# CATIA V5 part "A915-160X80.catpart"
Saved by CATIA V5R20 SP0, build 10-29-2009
Part number: A915-160X80
Source: Unknown
Property "A": "110.000"
Property "ARTICLENO": "A915-160X80"
Property "BOMINFO": "A915-160X80"
Property "CODE": "A915-160X80"
Property "CREATOR": "CADENAS GmbH"
Property "D": "13.500"
Property "D1": "20.000"
Property "FORM": "A"
Property "L": "80.000"
Property "L1": "40.000"
Property "L2": "0.000"
Property "LINA": "A915-160X80"
Property "NB": "A915-160X80"
Property "NBSYN": "$CODE."
Property "NN": "A915"
Property "NT": "VDI 3357 Wear Plates, steel"
Property "SCREW": "M12x25"
Property "SUPPLIER": "CF"
Property "T": "13.000"
Property "W": "160.000"
Bounding box of the stored display mesh (mm): x 0 to 20, y 0 to 80, z -80 to 80
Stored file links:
  C:\Users\borellobunino\Desktop\3D X SITO CF\A915\GSB_OILLESS_G22501160080\CATIAV5\A915-160X80.catpart
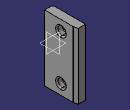
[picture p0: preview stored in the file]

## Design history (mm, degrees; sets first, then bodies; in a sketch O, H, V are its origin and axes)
Body1 "Geometry.1" (main body)
  Solid1 "A915-160X80.catpart": solid without history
